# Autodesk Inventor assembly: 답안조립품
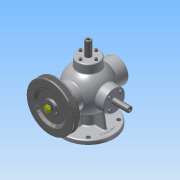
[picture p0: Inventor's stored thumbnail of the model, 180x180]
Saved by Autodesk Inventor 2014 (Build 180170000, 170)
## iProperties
Created: 2016-01
Part Number: 답안조립품
Document SubType Name: Assembly
Designer: Administrator
Mass: 3770.67 g
Surface Area: 2411.02 cm^2
Volume: 903.658 cm^3
Density: 4.17267 g/cm^3
Author: Administrator
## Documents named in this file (17)
- C:\Users\Administrator\Desktop\360108V1011\답안조립품.iam
- C:\Users\Administrator\Desktop\360108V1011\본체.ipt
- C:\Users\Administrator\Desktop\360108V1011\뒤커버.ipt
- C:\Users\Administrator\Desktop\360108V1011\베어링- 6202.ipt
- C:\Users\Administrator\Desktop\360108V1011\본체커버.ipt
- C:\Users\Administrator\Desktop\360108V1011\앞커버.ipt
- C:\Users\Administrator\Desktop\360108V1011\오일실.ipt
- C:\Users\Administrator\Desktop\360108V1011\축.ipt
- C:\Users\Administrator\Desktop\360108V1011\키-4x4.ipt
- C:\Users\Administrator\Desktop\360108V1011\V-벨트풀리.ipt
- C:\Users\Administrator\Desktop\360108V1011\슬라이드 커버.ipt
- C:\Users\Administrator\Desktop\360108V1011\슬라이드.ipt
- C:\Users\Administrator\Desktop\360108V1011\볼트 M4x0.7.ipt
- C:\Users\Administrator\Desktop\360108V1011\너트-M8x1.ipt
- C:\Users\Administrator\Desktop\360108V1011\와셔 8x17.ipt
- C:\Users\Administrator\Desktop\360108V1011\15스프링.ipt
- C:\Users\Administrator\Desktop\360108V1011\16스프링.ipt
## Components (20 placed, 4 different names)
1. V-벨트풀리:1 — 각도:2
2. M4x0.7x12:1
3. 15스프링:1
4. 16스프링:1
5. M4x0.7x12:2
6. M4x0.7x12:6
7. M4x0.7x12:7
8. M4x0.7x12:8
9. M4x0.7x12:4
10. M4x0.7x12:9
11. M4x0.7x12:10
12. M4x0.7x12:11
13. M4x0.7x12:3
14. M4x0.7x12:12
15. M4x0.7x12:13
16. M4x0.7x12:14
17. M4x0.7x12:5
18. M4x0.7x12:15
19. M4x0.7x12:16
20. M4x0.7x12:17
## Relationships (1: Angle 1)
- 각도:2 [Angle]: V-벨트풀리:1
